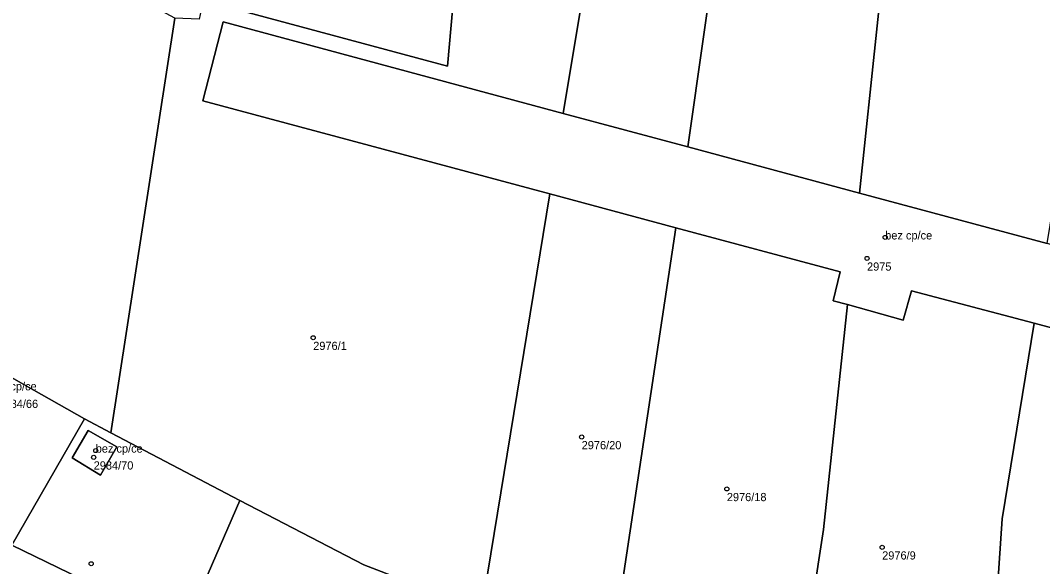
# Model space of a CAD drawing. Extents: x -878211 to -870363, y -1058464 to -1052522.
# Drawn here: x -873357.8 to -873233.3, y -1056087.5 to -1056021 of the extents above; entities that cross this region are included whole.
import ezdxf

# ---------------------------------------------------------------- set-up
doc = ezdxf.new("R2010")
doc.units = 0
for name, color, linetype in [('Vrstva 50', 7, 'Continuous'), ('Vrstva 51', 7, 'Continuous'), ('Vrstva 52', 7, 'Continuous')]:
    doc.layers.add(name, color=color, linetype=linetype)

msp = doc.modelspace()

# ---------------------------------------------------------------- linework, layer by layer
at = {"layer": 'Vrstva 50'}
for centre in [(-873252.45, -1056047.37994), (-873254.66, -1056049.93994), (-873322.12, -1056059.59994), (-873289.42, -1056071.68994), (-873348.86, -1056074.15994), (-873348.61, -1056073.33994), (-873271.74, -1056078.00994), (-873252.82, -1056085.11994), (-873349.16, -1056087.11994)]:
    msp.add_circle(centre, 0.25, dxfattribs=at)
at = {"layer": 'Vrstva 51'}
for points in [[(-873318.27, -1055935.12), (-873335.54, -1056018.53), (-873305.75, -1056026.51), (-873302.26, -1055987.38), (-873293.33, -1055944.95)], [(-873333.09, -1056021.11), (-873291.67, -1056032.28), (-873279.01, -1055956.19), (-873278.12, -1055950.93), (-873293.33, -1055944.95), (-873302.26, -1055987.38), (-873305.75, -1056026.51), (-873335.54, -1056018.53), (-873336, -1056020.81), (-873338.98, -1056020.68), (-873346.78, -1056071.17), (-873331.06, -1056079.42), (-873315.95, -1056087.25), (-873311.01, -1056089.16), (-873306.55, -1056090.87), (-873301.67, -1056093.08), (-873293.3, -1056042.09), (-873335.55, -1056030.74)], [(-873242.2, -1055961.87), (-873262.89, -1055955.57), (-873264.24, -1055961.22), (-873268.73, -1055981.87), (-873276.51, -1056036.37), (-873255.6, -1056042.01), (-873251.26, -1056001.19), (-873249.24, -1055986.01)], [(-873422.69, -1056031.38), (-873418.27, -1056033.17), (-873411.98, -1056036.95), (-873406.26, -1056039.94), (-873391.99, -1056047.4), (-873370.31, -1056057.99), (-873349.99, -1056069.49), (-873346.78, -1056071.17), (-873338.98, -1056020.68), (-873404.93, -1055985.24), (-873484.29, -1055957.15), (-873490.94, -1056014.57), (-873481.86, -1056016.97), (-873478.93, -1056017.14), (-873462.56, -1056021.67), (-873456.37, -1056022.93), (-873434.77, -1056027.26), (-873432.72, -1056027.9)], [(-873291.67, -1056032.28), (-873276.51, -1056036.37), (-873268.73, -1055981.87), (-873264.24, -1055961.22), (-873279.01, -1055956.19)], [(-873218.66, -1055969.11), (-873242.2, -1055961.87), (-873249.24, -1055986.01), (-873251.26, -1056001.19), (-873255.6, -1056042.01), (-873232.73, -1056048.14), (-873224.62, -1055998.43)], [(-873173.72, -1056064.03), (-873187.14, -1056060.35), (-873202.57, -1056056.21), (-873232.73, -1056048.14), (-873255.6, -1056042.01), (-873276.51, -1056036.37), (-873291.67, -1056032.28), (-873333.09, -1056021.11), (-873335.55, -1056030.74), (-873293.3, -1056042.09), (-873277.94, -1056046.21), (-873257.93, -1056051.59), (-873258.79, -1056055.12), (-873257.04, -1056055.54), (-873250.26, -1056057.44), (-873249.24, -1056053.87), (-873234.31, -1056057.82), (-873203.91, -1056065.98), (-873188.66, -1056070.07), (-873175.46, -1056073.68), (-873171.34, -1056074.79), (-873168.86, -1056065.36)], [(-873288.21, -1056099.16), (-873286.08, -1056100.1), (-873277.94, -1056046.21), (-873293.3, -1056042.09), (-873301.67, -1056093.08)], [(-873286.08, -1056100.1), (-873265.22, -1056109.34), (-873264.07, -1056109.68), (-873259.95, -1056082.97), (-873257.04, -1056055.54), (-873258.79, -1056055.12), (-873257.93, -1056051.59), (-873277.94, -1056046.21)], [(-873264.07, -1056109.68), (-873240.67, -1056118.23), (-873238.19, -1056081.64), (-873234.31, -1056057.82), (-873249.24, -1056053.87), (-873250.26, -1056057.44), (-873257.04, -1056055.54), (-873259.95, -1056082.97)], [(-873358.84, -1056084.87), (-873349.99, -1056069.49), (-873370.31, -1056057.99), (-873378.35, -1056075.24)], [(-873240.67, -1056118.23), (-873225.05, -1056124.01), (-873212.37, -1056127.9), (-873203.91, -1056065.98), (-873234.31, -1056057.82), (-873238.19, -1056081.64)], [(-873337.83, -1056095.04), (-873331.06, -1056079.42), (-873346.78, -1056071.17), (-873349.99, -1056069.49), (-873358.84, -1056084.87)], [(-873348.01, -1056076.33), (-873346.03, -1056072.9), (-873349.52, -1056070.88), (-873351.46, -1056074.24)], [(-873348.01, -1056076.33), (-873351.46, -1056074.24), (-873349.52, -1056070.88), (-873346.03, -1056072.9)], [(-873315.24, -1056105.68), (-873311.01, -1056089.16), (-873315.95, -1056087.25), (-873331.06, -1056079.42), (-873337.83, -1056095.04)]]:
    msp.add_lwpolyline(points, close=True, dxfattribs=at)
msp.add_lwpolyline([(-873358.95, -1056151.09), (-873357.25, -1056132.82), (-873355.68, -1056132.36), (-873352.16, -1056133.09), (-873333.51, -1056140.43), (-873313.43, -1056149.01), (-873310.74, -1056150.17), (-873310.23, -1056146.89), (-873312.65, -1056145.88), (-873335.8, -1056135.91), (-873356.11, -1056127.09), (-873356.7, -1056124.46), (-873354.85, -1056108.87), (-873352.99, -1056093.84), (-873352.25, -1056093.3), (-873351.24, -1056093.47), (-873348.34, -1056094.46), (-873329.11, -1056103.18), (-873305.26, -1056114.95), (-873304.57, -1056110.73), (-873315.24, -1056105.68), (-873337.83, -1056095.04), (-873358.84, -1056084.87)], dxfattribs=at)
at = {"layer": 'Vrstva 52'}
for points in [[(-873335.55, -1056030.74), (-873293.3, -1056042.09), (-873277.94, -1056046.21), (-873257.93, -1056051.59), (-873258.79, -1056055.12), (-873257.04, -1056055.54), (-873250.26, -1056057.44), (-873249.24, -1056053.87), (-873234.31, -1056057.82), (-873203.91, -1056065.98), (-873188.66, -1056070.07), (-873175.46, -1056073.68), (-873171.34, -1056074.79), (-873168.86, -1056065.36), (-873173.72, -1056064.03), (-873187.14, -1056060.35), (-873202.57, -1056056.21), (-873232.73, -1056048.14), (-873255.6, -1056042.01), (-873276.51, -1056036.37), (-873291.67, -1056032.28), (-873333.09, -1056021.11)], [(-873346.03, -1056072.9), (-873349.52, -1056070.88), (-873351.46, -1056074.24), (-873348.01, -1056076.33)]]:
    msp.add_lwpolyline(points, close=True, dxfattribs=at)

# ---------------------------------------------------------------- texts
at = {"layer": 'Vrstva 50'}
for s, p in [('bez cp/ce', (-873252.45, -1056047.629)), ('2975', (-873254.66, -1056051.429)), ('2976/1', (-873322.12, -1056061.089)), ('bez cp/ce', (-873361.53, -1056066.01)), ('2984/66', (-873360.46, -1056068.149)), ('bez cp/ce', (-873348.61, -1056073.59)), ('2976/20', (-873289.42, -1056073.179)), ('2984/70', (-873348.86, -1056075.649)), ('2976/18', (-873271.74, -1056079.499)), ('2976/9', (-873252.82, -1056086.609))]:
    msp.add_text(s, height=0.999996, dxfattribs=at).set_placement(p)

doc.saveas('drawing.dxf')
